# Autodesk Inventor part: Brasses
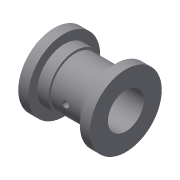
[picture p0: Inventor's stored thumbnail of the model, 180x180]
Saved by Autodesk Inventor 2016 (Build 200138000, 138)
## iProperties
Created: 2009-04
Part Number: Brasses
Document SubType Name: Modeling
Designer: Sham
Density: 1 g/cm^3
Material: Generic
Appearance: Default
Author: Sham
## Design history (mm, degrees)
sketch "Sketch1"
  geometry: L1 (0, 32)-(9, 32); L2 (0, 16)-(64, 16); L3 (64, 32)-(55, 32); L4 (55, 32)-(55, 24); L5 (55, 24)-(47, 24); L6 (19, 22)-(47, 22); L7 (47, 24)-(47, 22); L8 (19, 22)-(19, 24); L9 (19, 24)-(9, 24); L10 (9, 24)-(9, 32); L11 (0, 32)-(0, 16); L12 (64, 32)-(64, 16); L13 (-12.8, 0)-(76.8, 0) reference; 1 further point
  constraints: 24 end point, 7 parallel, 4 perpendicular, 1 collinear, 1 horizontal, 1 vertical alignment, 1 other
  dimensions: "d0" = 9 distance of L1.start L1.end; "d2" = 16 distance from line of L2 point (0, 0); "d3" = 64 distance of L2.start L2.end; "d4" = 24 distance from line of point (0, 0) L5; "d5" = 28 distance of L6.start L6.end; "d6" = 22 distance from line of point (0, 0) L6; "d7" = 8 distance of L4.end L5.end
revolve "Revolution1" sketch "Sketch1" stored, may be unused: angle "d8" = 90 deg
workplane "Work Plane1"
sketch "Sketch2"
  geometry: C1 r 4 at (-32, 0)
  constraints: 1 centre point
  dimensions: "d10" = 8 diameter of C1
extrude "Extrusion1" join sketch "Sketch2" stored distance "d11" = 10; taper "d12" = 0 deg
sketch "Sketch3"
  geometry: C1 r 4 at (0, 0) reference; C2 r 3 at (0, 0)
  constraints: 1 centre point, 1 coincident
  dimensions: "d13" = 6 diameter of C2
extrude "Extrusion2" cut sketch "Sketch3" stored distance "d14" = 10; taper "d15" = 0 deg
body "Solid1"
